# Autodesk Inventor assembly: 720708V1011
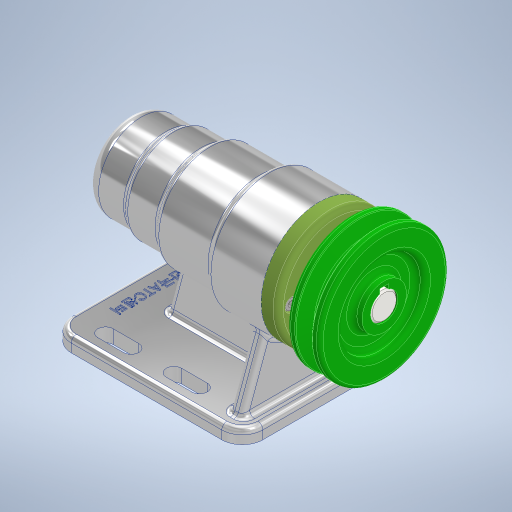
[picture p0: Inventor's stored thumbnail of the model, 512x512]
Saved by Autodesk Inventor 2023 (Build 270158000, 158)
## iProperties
Created: 2022-07
Part Number: 720708V1011
Document SubType Name: Assembly
Designer: owner
Author: owner
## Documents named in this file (12)
- C:\Users\owner\Desktop\720708V1011\720708V1011.iam
- C:\Users\owner\Desktop\720708V1011\본체.ipt
- C:\Users\owner\Desktop\720708V1011\V벨트풀리.ipt
- C:\Users\owner\Desktop\720708V1011\멈춤나사 M3.ipt
- C:\Users\owner\Desktop\720708V1011\베어링 6004.ipt
- C:\Users\owner\Desktop\720708V1011\베어링 51202.ipt
- C:\Users\owner\Desktop\720708V1011\볼트 M4.ipt
- C:\Users\owner\Desktop\720708V1011\어댑터슬리브.ipt
- C:\Users\owner\Desktop\720708V1011\오일 실 20x35x7.ipt
- C:\Users\owner\Desktop\720708V1011\축.ipt
- C:\Users\owner\Desktop\720708V1011\커버.ipt
- C:\Users\owner\Desktop\720708V1011\키 5x5.ipt
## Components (1 placed, 1 different names)
1. V벨트풀리:1 — 강체:8
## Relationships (1: WeldJoint 1)
- 강체:8 [WeldJoint]: V벨트풀리:1
